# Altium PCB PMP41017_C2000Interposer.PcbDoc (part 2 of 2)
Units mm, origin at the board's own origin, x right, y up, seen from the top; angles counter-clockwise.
Board outline 70 x 48.62 mm, 4 copper layers (Top, Mid1, Mid2, Bottom), stack 0.778 mm thick; 159 components, 259 nets, 698 pads, 194 vias.
Unrouted connection lines stored in the file: 8.
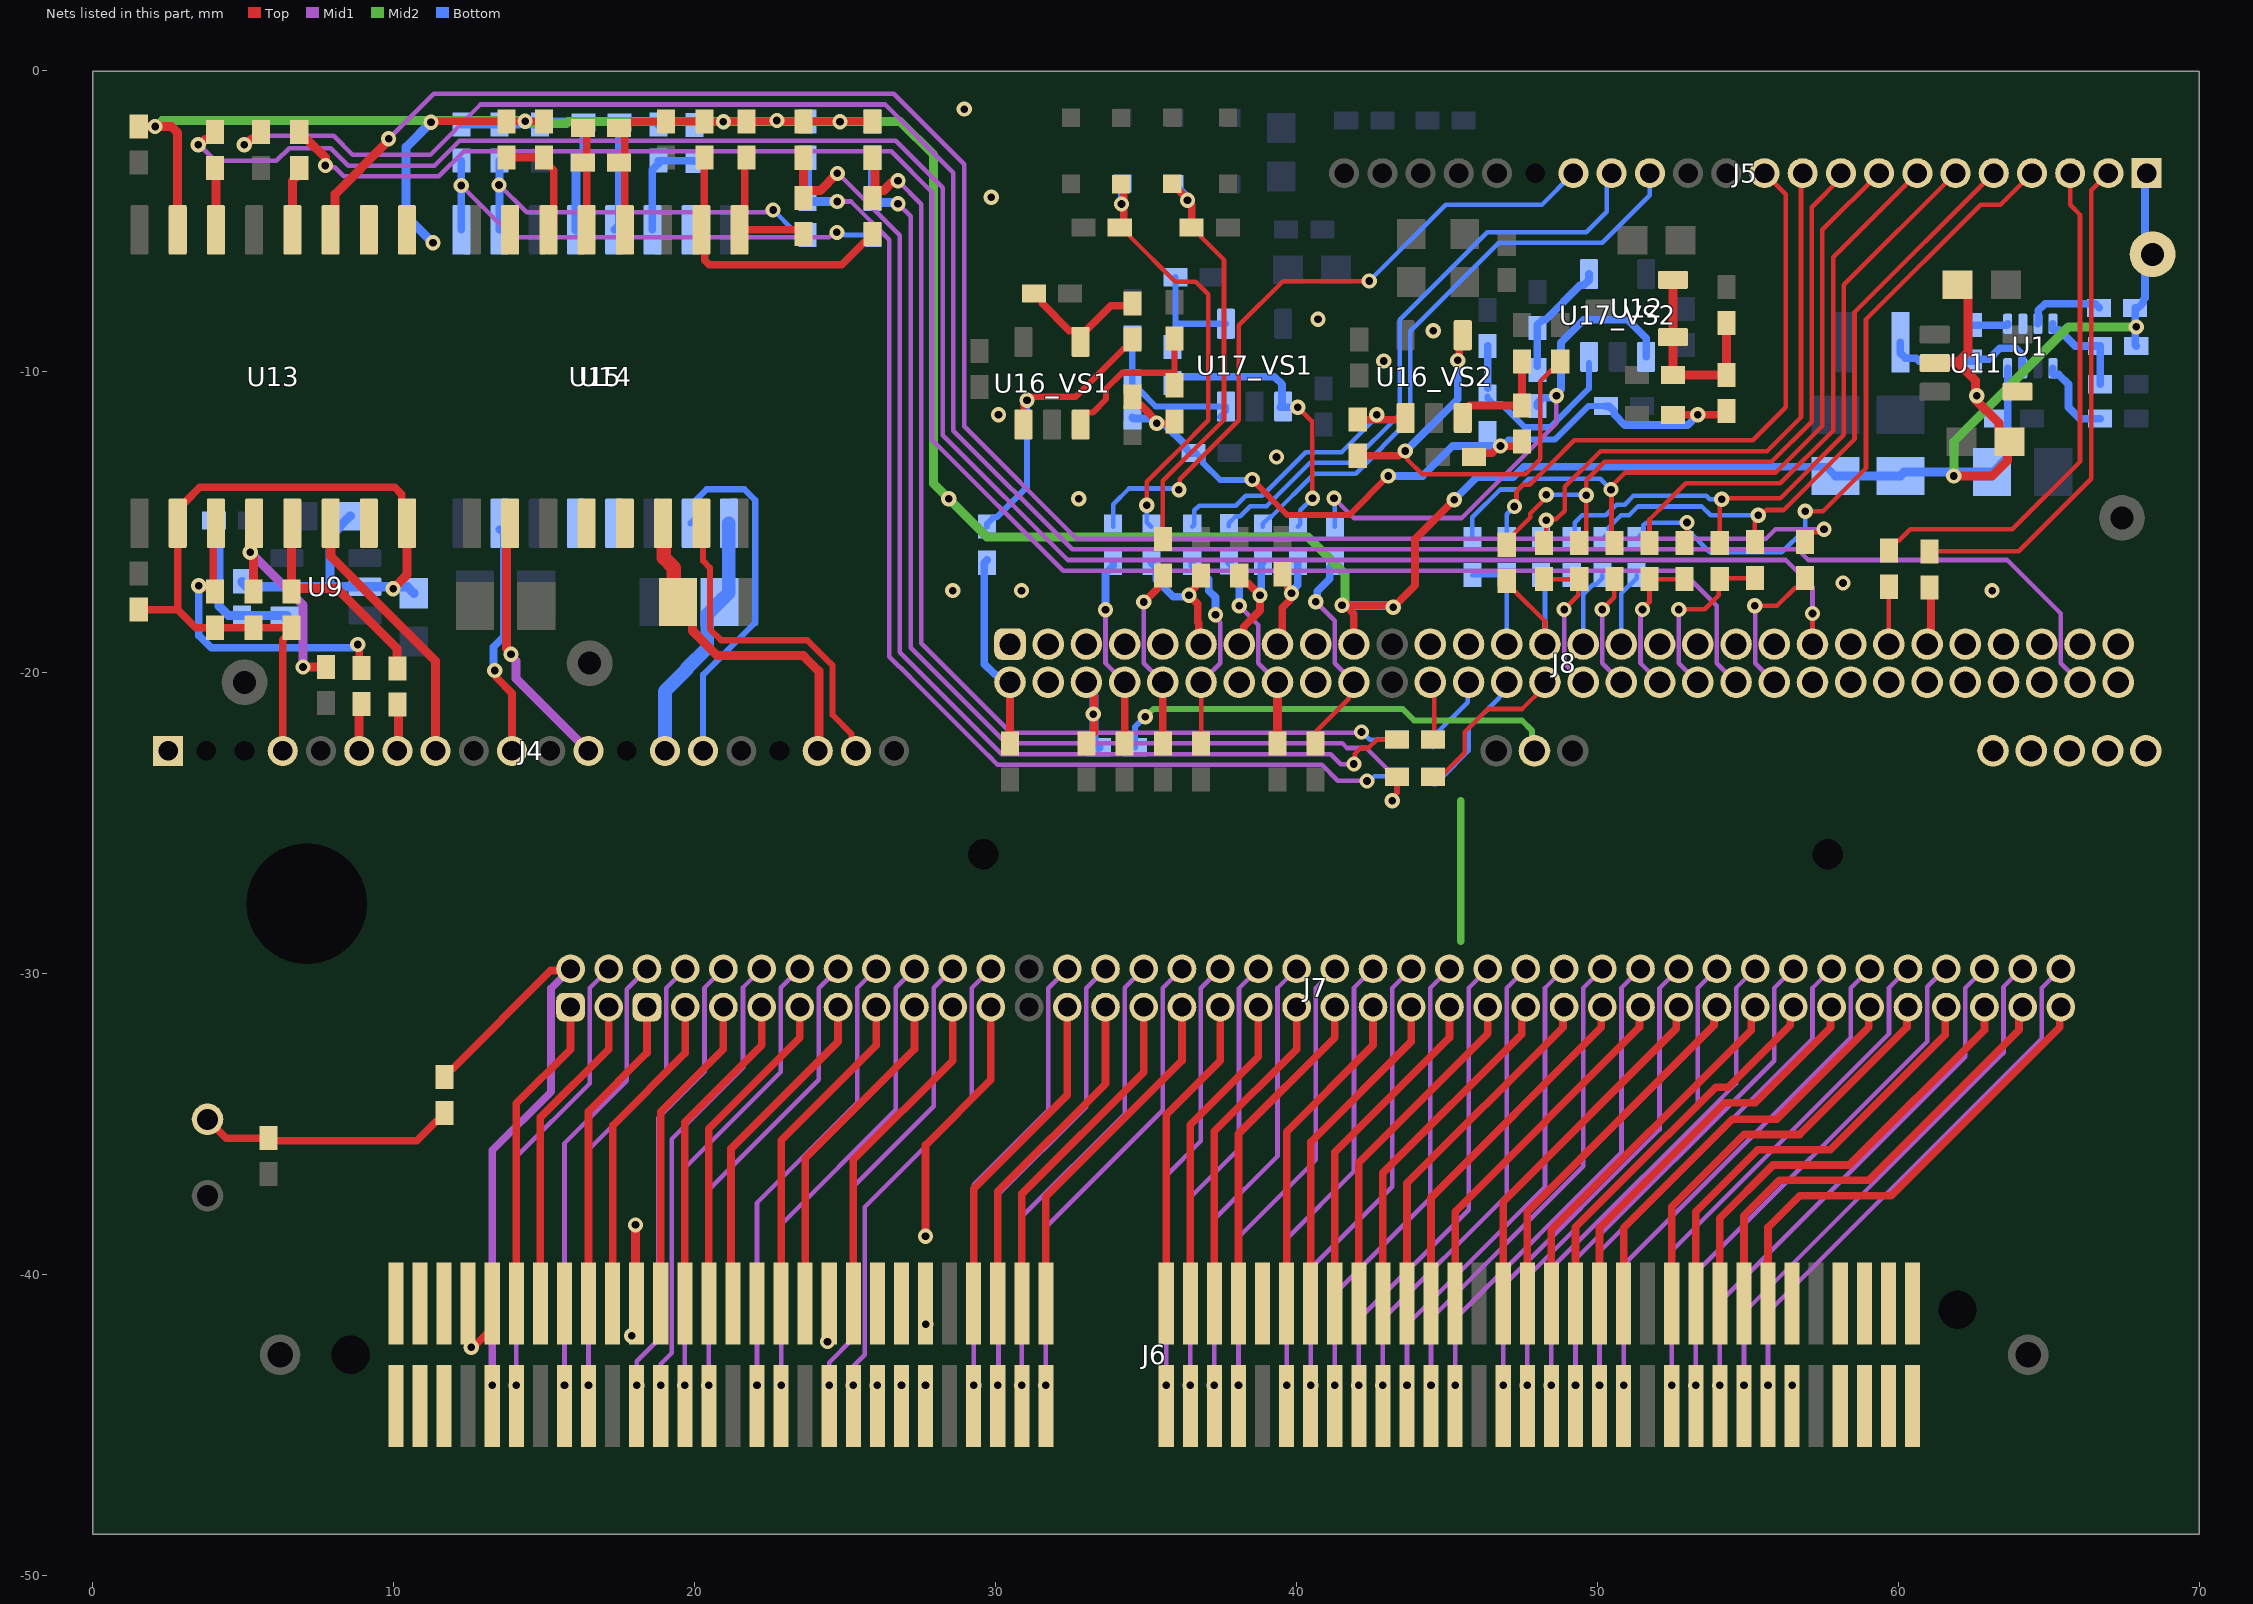
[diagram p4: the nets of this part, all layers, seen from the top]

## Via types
v1: diameter 0.508, hole 0.254, Top to Bottom, tented both sides, 194 vias

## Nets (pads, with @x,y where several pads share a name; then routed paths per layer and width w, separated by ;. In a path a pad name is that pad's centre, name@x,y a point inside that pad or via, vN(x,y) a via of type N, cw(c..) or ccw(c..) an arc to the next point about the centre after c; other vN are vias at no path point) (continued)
DGND-s: C1.1 C2.2 C5.2 C6.2 C105.2 C107.2 C111.2 C112.2 C113.2 C114.2 C115.2 C118.2 C119.2 C125.1 C126.1 C127.2 C128.2 J5.1 J6.10 J6.22 J6.38 J6.46 J7.23 J8.23 pad.5@63.15,-22.6 pad.5@64.42,-22.6 pad.5@65.69,-22.6 pad.5@66.96,-22.6 pad.5@68.23,-22.6 pad.9@68.453,-6.096 R3.1 R20.2 R68.2 R69.2 R70.2 R71.2 R79.1 R80.1 R81.1 R82.1 U1.4 U11.2 U13.15 U14.4 U15.4 | length 179.7
  Top w0.152: J6.22@18.034,-40.933 J6.22@18.073,-40.972 ; J6.46@27.673,-40.972 27.681,-40.98 v1(27.681,-41.656) J6.46@27.681,-41.739
  Top w0.254: v1(11.238,-1.709) 11.269,-1.677 C125.1@13.742,-1.677 R81.1@14.986,-1.677 ; v1(12.573,-42.418) 12.638,-42.418 13.273,-41.783 J6.10@13.273,-40.972 ; R79.1@17.491,-1.905 17.664,-1.732 17.867,-1.732 17.913,-1.686 19.041,-1.686 C127.2@19.05,-1.677 C112.2@20.32,-1.677 20.329,-1.686 v1(20.955,-1.686) ; R79.1@17.507,-1.905 17.68,-2.078 U14.4@17.68,-5.285 ; v1@20.946,-1.677 C111.2@21.717,-1.677 25.899,-1.677 R68.2@25.908,-1.686 ; v1(27.673,-38.735) 27.673,-35.7 29.845,-33.528 J7.23@29.845,-31.115 ; v1@41.496,-17.778 41.651,-17.778 41.91,-18.037 J8.23@41.91,-19.05 ; v1@41.496,-17.745 v1(41.512,-17.761) ; v1@41.651,-17.761 43.079,-17.761 43.145,-17.828 v1(43.214,-17.828) 43.942,-17.1 43.942,-15.558 v1(45.244,-14.256) v1@45.212,-14.224
  Top w0.3: C115.2@1.524,-1.848 2.61,-1.848 2.82,-2.058 U13.15@2.82,-5.285 ; v1(17.907,-42.037) 17.907,-41.981 18.006,-41.882 18.006,-41.039 J6.22@18.073,-40.972 ; J6.22@18.034,-40.933 v1(18.034,-38.354) ; v1(24.413,-42.231) 24.413,-42.175 24.473,-42.115 J6.38@24.473,-40.972 ; v1(61.849,-13.462) 63.119,-13.462 63.627,-12.954 63.627,-12.395 C107.2@63.703,-12.319 63.678,-12.319 63.353,-11.994 63.353,-11.708 62.567,-10.922 62.567,-10.287 61.993,-9.713 U11.2@61.214,-9.713 61.25,-9.677 61.985,-9.677 62.313,-9.349 C105.2@62.313,-7.437
  Mid2 w0.254: 45.466,-28.921 45.466,-24.257
  Mid2 w0.3: v1(2.067,-1.848) 2.123,-1.848 2.32,-1.651 11.124,-1.651 11.181,-1.709 v1(11.238,-1.709) 11.277,-1.669 11.424,-1.669 11.442,-1.651 v1@14.431,-1.651 ; v1(14.364,-1.677) 14.404,-1.717 14.551,-1.717 14.578,-1.744 15.736,-1.744 15.794,-1.686 v1(20.955,-1.686) 22.733,-1.686 v1(24.828,-1.686) 26.832,-1.686 27.94,-2.794 27.94,-13.716 29.718,-15.494 40.386,-15.494 41.616,-16.724 41.616,-17.601 41.512,-17.705 v1(41.512,-17.761) ; v1(61.849,-13.462) 61.849,-12.319 65.659,-8.509 v1(67.91,-8.509)
  Bottom w0.254: C113.2@12.245,-1.784 14.175,-1.784 14.233,-1.726 14.316,-1.726 v1(14.364,-1.677) ; v1@14.471,-1.784 C128.2@14.863,-1.784 14.97,-1.677 16.256,-1.677 R80.1@16.299,-1.72 C119.2@16.299,-3.028 ; v1(20.955,-1.686) R70.2@23.749,-1.686 R71.2@25.908,-1.686 ; v1(45.244,-14.256) 45.991,-13.509 47.199,-13.509 47.555,-13.154 57.604,-13.154 C6.2@57.912,-13.462 ; C2.2@63.119,-13.335 63.627,-12.827 63.627,-12.525 63.639,-12.513 U1.4@63.639,-9.884 ; R20.2@67.91,-9.144 67.875,-9.109 67.875,-8.509 R3.1@67.875,-7.874 67.975,-7.874 68.148,-7.701 68.148,-7.601 68.199,-7.55 68.199,-3.456 J5.1@68.255,-3.4
  Bottom w0.3: v1(2.067,-1.848) 2.123,-1.848 2.32,-1.651 11.033,-1.651 11.051,-1.669 11.198,-1.669 v1(11.238,-1.709) 10.414,-2.532 10.414,-4.826 v1(11.303,-5.715) ; U15.4@16.055,-5.285 16.055,-3.198 16.225,-3.028 C119.2@16.299,-3.028 ; C126.1@18.796,-1.784 18.894,-1.686 v1(20.955,-1.686) ; v1(41.512,-17.761) 41.526,-17.775 43.105,-17.775 43.158,-17.828 v1(43.214,-17.828) ; C6.2@57.912,-13.462 C5.2@60.071,-13.462 60.198,-13.335 C2.2@63.119,-13.335
  other v1: 28.575,-17.272 30.861,-17.272 63.119,-17.272 58.166,-17.018 28.448,-14.224 32.766,-14.224 39.339,-12.831 30.099,-11.43 62.611,-10.795 42.9,-9.643 44.543,-8.639 40.716,-8.255 29.861,-4.203 22.733,-1.651 28.956,-1.27
GNDc-p: C77.2 C88.2 C110.2 C120.1 C121.1 C122.1 J4.4 R5.1 U9.2 U13.2 U13.8 | length 32.8
  Top w0.254: C110.2@1.47,-17.907 2.82,-17.907 ; J4.4@6.31,-22.6 6.31,-18.901 6.604,-18.607 C120.1@6.604,-18.507 C121.1@5.334,-18.507 C122.1@4.064,-18.507 3.42,-18.507 2.82,-17.907 ; U13.8@10.44,-15.035 10.27,-14.864 10.27,-14.08 10.033,-13.843 3.556,-13.843 3.062,-14.337 2.993,-14.337 2.82,-14.51 U13.2@2.82,-15.035 2.82,-17.907
  Top w0.3: v1(9.978,-17.207) 9.978,-17.204 10.44,-16.742 U13.8@10.44,-15.035
  Bottom w0.3: R5.1@4.953,-16.963 4.953,-16.995 5.103,-17.145 7.874,-17.145 ; C88.2@8.566,-14.799 8.541,-14.799 8.216,-15.124 8.216,-15.149 7.874,-15.491 7.874,-17.145 ; C77.2@10.668,-17.361 10.452,-17.145 9.978,-17.145 U9.2@9.047,-17.145 7.874,-17.145
HV_BUS: J4.1
I-reso_VS1: D3_VS1.1 D5_VS1.1 R11.2 R83_VS1.2 | length 14.7
  Top w0.152: R83_VS1.2@34.128,-5.207 34.228,-5.207 34.452,-5.431 34.452,-5.486 35.976,-7.011 36.655,-7.011 37.068,-7.424 37.068,-11.617 36.086,-12.599 35.56,-13.125 35.027,-13.659 v1(35.027,-14.437)
  Top w0.203: R83_VS1.2@34.128,-5.207 R83_VS1.2@34.262,-5.073
  Top w0.254: R83_VS1.2@34.262,-5.073 34.262,-4.426 D5_VS1.1@34.262,-3.767
  Bottom w0.152: v1(35.027,-14.437) 35.027,-14.996 R11.2@35.179,-15.148
  Bottom w0.203: v1(34.185,-4.426) 34.213,-4.426 v1@34.199,-4.412 ; D3_VS1.1@34.199,-3.762 D3_VS1.1@34.213,-3.748
  Bottom w0.254: v1@34.199,-4.412 D3_VS1.1@34.199,-3.762
I-reso_VS2: D3_VS2.1 D5_VS2.1 R12.2 R83_VS2.2 | length 14
  Top w0.152: R12.2@35.56,-15.564 35.56,-13.628 37.592,-11.596 37.592,-6.28 36.843,-5.531 36.843,-5.431 36.619,-5.207 R83_VS2.2@36.519,-5.207
  Top w0.203: R83_VS2.2@36.519,-5.207 R83_VS2.2@36.519,-5.073
  Top w0.254: D5_VS2.1@35.872,-3.751 v1@36.323,-4.202 ; v1(36.38,-4.302) 36.519,-4.441 R83_VS2.2@36.519,-5.073
  Bottom w0.254: D3_VS2.1@35.941,-3.767 36.331,-4.157 36.331,-4.254 v1(36.38,-4.302)
ISEC1: J5.15 R13.2 | length 20.1
  Bottom w0.152: R13.2@37.752,-15.134 37.752,-15.034 37.976,-14.811 38.06,-14.811 38.065,-14.806 38.134,-14.806 38.468,-14.472 39.006,-14.472 40.45,-13.028 41.822,-13.028 43.43,-11.42 43.43,-8.266 46.337,-5.359 49.632,-5.359 50.315,-4.676 50.315,-3.56 J5.15@50.475,-3.4
ISEC2: J5.14 R14.2 | length 19.9
  Bottom w0.152: R14.2@38.884,-15.151 38.884,-15.051 39.107,-14.827 39.154,-14.827 40.597,-13.383 41.965,-13.383 43.783,-11.566 43.783,-8.65 46.717,-5.715 50.165,-5.715 51.745,-4.135 J5.14@51.745,-3.4
LLC-DRV-1H: J4.19 U14.15 | length 10.8
  Top w0.203: U14.15@20.281,-15.621 20.281,-16.284 20.507,-16.51 20.507,-18.551 20.88,-18.923 23.749,-18.923 24.511,-19.685 24.511,-19.69 24.582,-19.76 24.582,-21.407 25.208,-22.033 25.208,-22.448 J4.19@25.36,-22.6
LLC-DRV-1L: J4.12 U14.10 | length 8.9
  Top w0.3: U14.10@13.87,-15.035 13.744,-15.161 13.744,-19.181 13.897,-19.334 v1(13.897,-19.39) ; J4.12@16.47,-22.6 J4.12@16.47,-22.411
  Mid1 w0.3: v1(13.897,-19.39) 13.897,-19.446 14.065,-19.614 14.065,-20.195 J4.12@16.47,-22.6
LLC-DRV-2H: J4.15 U15.10 | length 12.2
  Bottom w0.203: U15.10@19.865,-15.035 20.064,-14.837 20.064,-14.241 20.4,-13.905 21.652,-13.905 22.014,-14.267 22.014,-18.333 20.28,-20.067 J4.15@20.28,-22.6
LLC-DRV-2L: J4.10 U15.15 | length 7.8
  Top w0.254: v1(13.358,-19.929) 13.407,-19.977 13.407,-20.157 13.93,-20.68 J4.10@13.93,-22.6
  Bottom w0.254: v1(13.358,-19.929) 13.313,-19.883 13.313,-19.148 13.665,-18.796 13.665,-15.39 U15.15@13.515,-15.24
LLC-SW1: C116.2 J4.18 U14.14 | length 11.4
  Top w0.3: C116.2@19.444,-17.653 19.929,-18.138 19.929,-18.615 20.744,-19.431 23.614,-19.431 24.13,-19.947 24.13,-22.56 J4.18@24.09,-22.6
  Top w0.483: U14.14@18.95,-15.035 18.966,-15.051 18.966,-16.172 19.304,-16.51 19.304,-17.513 C116.2@19.444,-17.653
LLC-SW2: C117.2 J4.14 U15.9 | length 8.4
  Bottom w0.457: J4.14@19.01,-22.6 19.01,-20.614 19.747,-19.877 19.747,-19.846 20.422,-19.171 20.422,-18.059 C117.2@20.828,-17.653 21.135,-17.346 U15.9@21.135,-15.035
MCU_A1: J6.11 J7.4 | length 15.1
  Mid1 w0.152: v1(14.073,-43.688) 14.073,-36.092 16.51,-33.655 16.51,-30.48 J7.4@17.145,-29.845
MCU_A3: J6.39 J7.24 | length 15.7
  Mid1 w0.152: v1(25.273,-43.688) 25.273,-43.053 25.654,-42.672 25.654,-37.757 29.21,-34.201 29.21,-30.48 J7.24@29.845,-29.845
MCU_A3_1: C89.2 J8.24 R18.1 | length 7.4
  Top w0.152: C89.2@40.457,-22.352 40.681,-22.128 40.681,-21.93 41.738,-20.873 41.738,-20.492 J8.24@41.91,-20.32
  Mid1 w0.152: v1(40.64,-17.643) 41.276,-18.279 41.276,-19.686 J8.24@41.91,-20.32
  Bottom w0.254: v1(40.64,-17.643) 40.686,-17.597 40.686,-17.3 41.102,-16.884 41.102,-16.521 R18.1@41.275,-16.348
MCU_A4: J6.17 J7.8 | length 15.2
  Mid1 w0.152: v1(16.473,-43.688) 16.473,-35.851 19.05,-33.274 19.05,-30.48 J7.8@19.685,-29.845
MCU_A4_1: J8.8
MCU_A5: J6.21 J7.10 | length 15
  Mid1 w0.152: v1(18.073,-43.688) 18.073,-42.887 18.796,-42.164 18.796,-34.798 20.327,-33.267 20.327,-30.473 J7.10@20.955,-29.845
MCU_A5_1: C74.2 J8.10 R1.1 | length 4.6
  Top w0.254: C74.2@33.02,-22.352 33.02,-22.252 33.274,-21.998 33.274,-20.789 33.02,-20.535 J8.10@33.02,-20.32
  Bottom w0.3: J8.10@33.02,-20.32 33.02,-20.523 33.274,-20.777 33.274,-22.329 33.424,-22.479 R1.1@33.436,-22.479
  other v1: 33.247,-21.376
MCU_A6: J6.23 J7.12 | length 15.2
  Mid1 w0.152: v1(18.873,-43.688) 18.873,-42.976 19.24,-42.609 19.24,-35.497 21.606,-33.131 21.606,-30.464 J7.12@22.225,-29.845
MCU_A6_1: C75.2 J8.12 R2.1 | length 6.4
  Top w0.254: C75.2@34.29,-22.352 J8.12@34.29,-20.32
  Mid1 w0.152: v1(33.655,-17.907) 33.655,-19.685 J8.12@34.29,-20.32
  Bottom w0.254: v1(33.655,-17.907) 33.655,-16.702 33.909,-16.448 R2.1@33.909,-16.348
MCU_A7: J6.33 J7.20 | length 15.7
  Mid1 w0.152: v1(22.873,-43.688) 22.873,-38.341 26.682,-34.532 26.682,-30.468 J7.20@27.305,-29.845
MCU_A7_1: C82.2 J8.20 R13.1 | length 6.7
  Top w0.3: C82.2@39.37,-22.352 J8.20@39.37,-20.32
  Mid1 w0.152: v1(38.1,-17.78) 38.736,-18.416 38.736,-19.686 J8.20@39.37,-20.32
  Bottom w0.254: R13.1@37.752,-16.334 37.925,-16.507 37.925,-16.708 38.1,-16.883 v1(38.1,-17.78)
MCU_A8: J6.30 J7.15 | length 11.4
  Top w0.254: J6.30@21.273,-40.972 21.209,-40.908 21.209,-35.814 24.765,-32.258 J7.15@24.765,-31.115
MCU_A8_1: C76.2 J8.15 R11.1 | length 4.8
  Top w0.254: J8.15@36.83,-19.05 36.758,-18.978 36.758,-18.349 36.725,-18.315 36.725,-17.719 v1(36.43,-17.424) 36.43,-17.375 36.657,-17.148 36.657,-16.937 C76.2@36.83,-16.764
  Bottom w0.254: R11.1@35.179,-16.348 35.344,-16.513 35.344,-16.914 35.902,-17.472 36.381,-17.472 v1(36.43,-17.424) ; J8.15@36.83,-19.05 J8.15@36.83,-18.835
MCU_A9: J6.34 J7.17 | length 11.2
  Top w0.254: J6.34@22.873,-40.972 22.873,-35.547 26.035,-32.385 J7.17@26.035,-31.115
MCU_A9_1: C84.2 J8.17 R14.1 | length 4.3
  Top w0.254: J8.17@38.1,-19.05 38.252,-18.898 38.252,-18.469 38.788,-17.934 v1(38.788,-17.424) 38.401,-17.037 38.273,-17.037 38.1,-16.864 C84.2@38.1,-16.764
  Bottom w0.254: J8.17@38.1,-19.05 J8.17@38.1,-18.835 ; v1(38.788,-17.424) 38.836,-17.376 38.836,-16.399 R14.1@38.884,-16.351
MCU_A10: J6.25 J7.14 | length 15.4
  Mid1 w0.152: v1(19.673,-43.688) 19.673,-36.461 22.862,-33.272 22.862,-30.478 J7.14@23.495,-29.845
MCU_A10_1: C78.2 J8.14 R12.1 | length 6.1
  Top w0.254: v1(34.926,-17.653) 35.387,-17.192 35.387,-16.937 R12.1@35.56,-16.764 ; C78.2@35.56,-22.352 J8.14@35.56,-20.32
  Mid1 w0.152: v1(34.926,-17.653) 34.926,-19.686 J8.14@35.56,-20.32
MCU_A12: J6.37 J7.22 | length 15.5
  Mid1 w0.152: v1(24.473,-43.688) 24.473,-42.926 25.273,-42.126 25.273,-37.084 27.942,-34.415 27.942,-30.478 J7.22@28.575,-29.845
MCU_A12_1: J8.22
MCU_B0: J6.31 J7.18 | length 15.5
  Mid1 w0.152: v1(22.073,-43.688) 22.073,-37.617 25.4,-34.29 25.4,-30.48 J7.18@26.035,-29.845
MCU_B0_1: J8.18
MCU_B2: J6.14 J7.3 | length 10.8
  Top w0.254: J6.14@14.873,-40.972 14.873,-34.784 17.145,-32.512 J7.3@17.145,-31.115
MCU_B3: J6.12 J7.1 | length 10.6
  Top w0.254: J6.12@14.073,-40.972 14.073,-34.314 15.875,-32.512 J7.1@15.875,-31.115
MCU_B4: J6.20 J7.7 | length 10.9
  Top w0.254: J6.20@17.273,-40.972 17.272,-40.971 17.272,-35.052 19.685,-32.639 J7.7@19.685,-31.115
MCU_B4_1: J8.7
MCU_B5: J6.26 J7.11 | length 10.9
  Top w0.254: J6.26@19.673,-40.972 19.673,-34.937 22.225,-32.385 J7.11@22.225,-31.115
MCU_B5_1: J8.11
MCU_B6: J6.15 J7.6 | length 15
  Mid1 w0.152: v1(15.673,-43.688) 15.673,-35.635 17.742,-33.566 17.742,-30.518 J7.6@18.415,-29.845
MCU_B6_1: C85.2 J8.6 R15.1 | length 6.6
  Top w0.254: C85.2@30.48,-22.352 J8.6@30.48,-20.32
  Bottom w0.254: R15.1@29.718,-16.256 29.625,-16.349 29.625,-19.712 29.97,-20.057 30.001,-20.057 30.265,-20.32 J8.6@30.48,-20.32
MCU_B10: J6.27 J7.16 | length 15.6
  Mid1 w0.152: v1(20.473,-43.688) 20.473,-37.185 24.123,-33.535 24.123,-30.487 J7.16@24.765,-29.845
MCU_B10_1: C87.2 J8.16 R17.1 | length 6.7
  Top w0.152: C87.2@36.83,-22.352 J8.16@36.83,-20.32
  Mid1 w0.152: J8.16@36.83,-20.32 37.464,-19.686 37.464,-18.325 37.309,-18.17 v1(37.309,-18.073)
  Bottom w0.254: R17.1@36.537,-16.348 36.537,-16.448 36.71,-16.621 36.81,-16.621 37.084,-16.895 37.084,-17.274 37.309,-17.499 v1(37.309,-18.073)
MCU_B11: J6.24 J7.9 | length 10.7
  Top w0.254: J6.24@18.873,-40.972 18.873,-34.594 20.955,-32.512 J7.9@20.955,-31.115
MCU_B11_1: J8.9
MCU_B12: J6.18 J7.5 | length 10.7
  Top w0.254: J6.18@16.473,-40.972 16.473,-34.581 18.415,-32.639 J7.5@18.415,-31.115
MCU_B12_1: J8.5
MCU_B14: J6.36 J7.19 | length 11.4
  Top w0.254: J6.36@23.673,-40.972 23.673,-36.144 27.305,-32.512 J7.19@27.305,-31.115
MCU_B14_1: C86.2 J8.19 R16.1 | length 3.6
  Top w0.254: J8.19@39.37,-19.05 39.522,-18.898 39.522,-17.84 39.789,-17.573 39.789,-17.338 39.838,-17.29 39.716,-17.168 39.716,-17.002 39.616,-16.902 C86.2@39.543,-16.902
  Bottom w0.254: v1(39.838,-17.359) 39.838,-17.302 40.047,-17.092 R16.1@40.047,-16.348
MCU_C1: J6.28 J7.13 | length 11.1
  Top w0.254: J6.28@20.473,-40.972 20.473,-35.153 23.495,-32.131 J7.13@23.495,-31.115
MCU_C1_1: J8.13
MCU_C14: J6.40 J7.21 | length 11.2
  Top w0.254: J6.40@25.273,-40.972 25.273,-36.195 28.575,-32.893 J7.21@28.575,-31.115
MCU_C14_1: J8.21
MCU_DACA: J6.9 J7.2 R60.2 | length 20.7
  Top w0.254: R60.2@11.684,-33.436 11.684,-33.336 11.857,-33.163 11.957,-33.163 15.223,-29.897 15.823,-29.897 J7.2@15.875,-29.845
  Mid1 w0.254: v1(13.273,-43.688) 13.273,-35.876 15.227,-33.922 15.227,-30.493 J7.2@15.875,-29.845
MCU_EMU0_3: J6.2
MCU_EMU1_3: J6.1
MCU_GPIO0: J6.49 J7.28 | length 15.1
  Mid1 w0.152: v1(29.273,-43.688) 29.273,-37.021 31.747,-34.547 31.747,-30.483 J7.28@32.385,-29.845
MCU_GPIO0_1: J8.28 R30.2 | length 2
  Top w0.152: J8.28@44.45,-20.32 44.577,-20.447 44.577,-22.19 R30.2@44.542,-22.225
MCU_GPIO1: J6.51 J7.30 | length 15.3
  Mid1 w0.152: v1(30.073,-43.688) 30.099,-43.662 30.099,-37.338 33.009,-34.428 33.009,-30.491 J7.30@33.655,-29.845
MCU_GPIO1_1: J8.30 R32.2 | length 2.6
  Bottom w0.152: R32.2@44.542,-22.479 44.635,-22.386 44.635,-22.04 45.691,-20.984 45.691,-20.349 J8.30@45.72,-20.32
MCU_GPIO2: J6.53 J7.32 | length 15.5
  Mid1 w0.152: v1(30.873,-43.688) 30.873,-38.088 34.292,-34.669 34.292,-30.478 J7.32@34.925,-29.845
MCU_GPIO2_1: J8.32 R33.2 | length 4.5
  Bottom w0.152: R33.2@44.542,-23.7 44.642,-23.7 44.866,-23.477 44.866,-23.454 45.72,-22.6 45.72,-21.844 46.737,-20.827 46.737,-20.816 46.99,-20.563 J8.32@46.99,-20.32
MCU_GPIO3: J6.55 J7.34 | length 15.7
  Mid1 w0.152: v1(31.673,-43.688) 31.673,-38.431 35.56,-34.544 35.56,-30.48 J7.34@36.195,-29.845
MCU_GPIO3_1: J8.34 R35.2 | length 5.6
  Top w0.152: R35.2@44.542,-23.465 44.612,-23.395 44.866,-23.395 45.593,-22.668 45.593,-21.971 46.355,-21.209 47.498,-21.209 48.26,-20.447 J8.34@48.26,-20.32
  Bottom w0.152: J8.34@48.128,-20.32 J8.34@48.26,-20.32
MCU_GPIO4: J6.50 J7.27 | length 11.1
  Top w0.254: J6.50@29.273,-40.972 29.273,-37.148 32.385,-34.036 J7.27@32.385,-31.115
MCU_GPIO4_1: J8.27
MCU_GPIO5: J6.52 J7.29 | length 11.3
  Top w0.254: J6.52@30.073,-40.972 30.073,-37.237 33.655,-33.655 J7.29@33.655,-31.115
MCU_GPIO5_1: J8.29
MCU_GPIO6: J6.54 J7.31 | length 11.5
  Top w0.254: J6.54@30.873,-40.972 30.873,-37.326 34.925,-33.274 J7.31@34.925,-31.115
MCU_GPIO6_1: J8.31 R7.2 R99.2 | length 3.4
  Bottom w0.152: R7.2@45.847,-16.756 R99.2@46.99,-16.756 J8.31@46.99,-19.05
MCU_GPIO7: J6.56 J7.33 | length 11.7
  Top w0.254: J6.56@31.673,-40.972 31.673,-37.415 36.195,-32.893 J7.33@36.195,-31.115
MCU_GPIO7_1: J8.33 R23.2 R100.2 | length 5.2
  Top w0.152: R23.2@46.99,-16.948 46.99,-17.048 47.214,-17.272 47.244,-17.272 48.26,-18.288 J8.33@48.26,-19.05
  Bottom w0.152: R100.2@48.133,-16.756 48.26,-16.883 J8.33@48.26,-19.05
  Bottom w0.254: J8.33@48.133,-18.923 J8.33@48.26,-19.05
MCU_GPIO8: J6.57 J7.36 | length 14.6
  Mid1 w0.152: v1(35.673,-43.688) 35.673,-36.717 36.825,-35.565 36.825,-30.485 J7.36@37.465,-29.845
MCU_GPIO8_1: J8.36 R8.2 R37.2 | length 5.1
  Top w0.152: R8.2@48.231,-16.891 48.814,-16.891 R37.2@49.398,-16.891 49.364,-16.925 49.364,-17.43 v1(48.895,-17.899)
  Mid1 w0.152: v1(48.895,-17.899) 48.895,-19.685 J8.36@49.53,-20.32
MCU_GPIO9: J6.59 J7.38 | length 14.8
  Mid1 w0.152: v1(36.473,-43.688) 36.473,-37.441 38.092,-35.822 38.092,-30.488 J7.38@38.735,-29.845
MCU_GPIO9_1: J8.38 R38.2 | length 3.9
  Top w0.152: v1(50.165,-17.899) 50.565,-17.498 R38.2@50.565,-16.891
  Mid1 w0.152: v1(50.165,-17.899) 50.165,-19.685 J8.38@50.8,-20.32
MCU_GPIO10: J6.61 J7.40 | length 15
  Mid1 w0.152: v1(37.273,-43.688) 37.273,-38.165 39.37,-36.068 39.37,-30.48 J7.40@40.005,-29.845
MCU_GPIO10_1: J8.40 R9.2 R40.2 | length 5.3
  Top w0.152: R9.2@52.9,-16.891 R40.2@51.733,-16.891 51.733,-17.632 ; 51.733,-17.632 51.733,-17.665 v1(51.499,-17.899) 51.499,-17.866 51.733,-17.632
  Mid1 w0.152: v1(51.499,-17.899) 51.436,-17.962 51.436,-19.686 J8.40@52.07,-20.32
MCU_GPIO11: J6.63 J7.42 | length 15.2
  Mid1 w0.152: v1(38.073,-43.688) 38.073,-38.762 40.64,-36.195 40.64,-30.48 J7.42@41.275,-29.845
MCU_GPIO11_1: J8.42 R24.2 R41.2 | length 5.9
  Top w0.152: v1(52.706,-17.899) 53.567,-17.899 54.035,-17.43 54.035,-16.924 R41.2@54.068,-16.891 54.103,-16.856 R24.2@55.235,-16.856
  Mid1 w0.152: v1(52.706,-17.899) 52.706,-19.686 J8.42@53.34,-20.32
MCU_GPIO12: J6.58 J7.35 | length 10.6
  Top w0.254: J6.58@35.673,-40.972 35.673,-34.685 37.465,-32.893 J7.35@37.465,-31.115
MCU_GPIO12_1: J8.35 R10.2 R101.2 | length 3.3
  Bottom w0.152: R10.2@49.149,-16.856 49.53,-17.237 49.53,-17.391 ; J8.35@49.53,-19.05 49.53,-17.391 ; R101.2@50.165,-16.756 50.165,-16.856 49.941,-17.08 49.841,-17.08 49.53,-17.391
MCU_GPIO13: J6.60 J7.37 | length 10.8
  Top w0.254: J6.60@36.473,-40.972 36.473,-35.028 38.735,-32.766 J7.37@38.735,-31.115
MCU_GPIO13_1: J8.37 R102.2 | length 2.5
  Bottom w0.152: J8.37@50.8,-19.05 50.8,-17.364 51.308,-16.856 R102.2@51.308,-16.756
MCU_GPIO14: J6.62 J7.39 | length 11
  Top w0.254: J6.62@37.273,-40.972 37.273,-35.244 40.005,-32.512 J7.39@40.005,-31.115
MCU_GPIO14_1: J8.39
MCU_GPIO15: J6.64 J7.41 | length 11.2
  Top w0.254: J6.64@38.073,-40.972 38.073,-35.333 41.275,-32.131 J7.41@41.275,-31.115
MCU_GPIO15_1: J8.41
MCU_GPIO16: J6.67 J7.44 | length 15
  Mid1 w0.152: v1(39.673,-43.688) 39.673,-38.813 41.912,-36.574 41.912,-30.478 J7.44@42.545,-29.845
MCU_GPIO16_1: J8.44 R46.2 | length 62.2
  Top w0.3: R46.2@6.858,-2.032 6.858,-2.132 7.008,-2.282 7.123,-2.282 7.733,-2.891 7.733,-3.139 v1(7.728,-3.143)
  Mid1 w0.152: v1(7.728,-3.143) 7.791,-3.206 8.043,-3.206 8.341,-3.505 11.501,-3.505 12.333,-2.673 26.534,-2.673 27.889,-4.028 27.889,-12.253 32.248,-16.612 52.807,-16.612 53.975,-17.78 53.975,-19.685 J8.44@54.61,-20.32
MCU_GPIO17: J6.69 J7.46 | length 15.2
  Mid1 w0.152: v1(40.473,-43.688) 40.473,-39.791 43.18,-37.084 43.18,-30.48 J7.46@43.815,-29.845
MCU_GPIO17_1: J8.46 R48.1 | length 4.9
  Top w0.152: v1(55.235,-17.78) 55.972,-17.78 56.572,-17.18 56.672,-17.18 56.896,-16.956 R48.1@56.896,-16.856
  Mid1 w0.152: v1(55.235,-17.78) 55.246,-17.791 55.246,-19.686 J8.46@55.88,-20.32
MCU_GPIO18: J6.71 J7.48 | length 15.4
  Mid1 w0.152: v1(41.273,-43.688) 41.273,-40.642 44.45,-37.465 44.45,-30.48 J7.48@45.085,-29.845
MCU_GPIO18_1: J8.48
MCU_GPIO19: J6.73 J7.50 | length 15.6
  Mid1 w0.152: v1(42.073,-43.688) 42.073,-41.493 45.72,-37.846 45.72,-30.48 J7.50@46.355,-29.845
MCU_GPIO19_1: J8.50
MCU_GPIO20: J6.68 J7.43 | length 11
  Top w0.254: J6.68@39.673,-40.972 39.673,-35.257 42.545,-32.385 J7.43@42.545,-31.115
MCU_GPIO20_1: J8.43
MCU_GPIO21: J6.70 J7.45 | length 11.2
  Top w0.254: J6.70@40.473,-40.972 40.473,-35.6 43.815,-32.258 J7.45@43.815,-31.115
MCU_GPIO21_1: J8.45
MCU_GPIO22: J6.72 J7.47 | length 11.4
  Top w0.254: J6.72@41.273,-40.972 41.273,-35.943 45.085,-32.131 J7.47@45.085,-31.115
MCU_GPIO22_1: J8.47 R43.2 | length 68.3
  Top w0.152: J8.47@57.15,-19.05 v1(57.15,-18.034)
  Top w0.3: v1(3.505,-2.455) 3.561,-2.455 3.735,-2.282 3.914,-2.282 4.064,-2.132 R43.2@4.064,-2.032
  Mid1 w0.152: v1(3.505,-2.455) 3.535,-2.455 4.069,-2.989 6.097,-2.989 6.52,-2.565 7.905,-2.565 8.489,-3.15 11.353,-3.15 12.186,-2.317 26.681,-2.317 28.245,-3.881 28.245,-12.106 32.395,-16.256 56.261,-16.256 57.15,-17.145 v1(57.15,-18.034)
MCU_GPIO23: J6.74 J7.49 | length 11.6
  Top w0.254: J6.74@42.073,-40.972 42.073,-36.286 46.355,-32.004 J7.49@46.355,-31.115
MCU_GPIO23_1: J8.49
MCU_GPIO24: J6.75 J7.52 | length 15.8
  Mid1 w0.152: v1(42.873,-43.688) 42.873,-41.493 46.99,-37.376 46.99,-30.48 J7.52@47.625,-29.845
MCU_GPIO24_1: J8.52
MCU_GPIO25: J6.77 J7.54 | length 16
  Mid1 w0.152: v1(43.673,-43.688) 43.673,-41.671 48.26,-37.084 48.26,-30.48 J7.54@48.895,-29.845
MCU_GPIO25_1: J8.54
MCU_GPIO26: J6.79 J7.56 | length 16.2
  Mid1 w0.152: v1(44.473,-43.688) 44.473,-41.468 49.53,-36.41 49.53,-30.48 J7.56@50.165,-29.845
MCU_GPIO26_1: J8.56
MCU_GPIO27: J6.81 J7.58 | length 16.4
  Mid1 w0.152: v1(45.273,-43.688) 45.273,-41.468 50.803,-35.938 50.803,-30.477 J7.58@51.435,-29.845
MCU_GPIO27_1: J8.58
MCU_GPIO28: J6.76 J7.51 | length 11.8
  Top w0.254: J6.76@42.873,-40.972 42.873,-36.629 47.491,-32.011 47.491,-31.249 J7.51@47.625,-31.115
MCU_GPIO28_1: J8.51 R50.2 | length 1.9
  Top w0.152: J8.51@59.69,-19.05 R50.2@59.69,-17.145
MCU_GPIO29: J6.78 J7.53 | length 12
  Top w0.254: J6.78@43.673,-40.972 43.673,-36.972 48.86,-31.785 48.86,-31.15 J7.53@48.895,-31.115
MCU_GPIO29_1: J8.53 R52.1 | length 1.5
  Top w0.254: J8.53@60.96,-19.05 61.087,-18.923 R52.1@61.087,-17.566
MCU_GPIO30: J6.80 J7.55 | length 12.2
  Top w0.254: J6.80@44.473,-40.972 44.473,-37.442 50.13,-31.785 50.13,-31.15 J7.55@50.165,-31.115
MCU_GPIO30_1: J8.55
MCU_GPIO31: J6.82 J7.57 | length 12.4
  Top w0.254: J6.82@45.273,-40.972 45.273,-37.912 51.4,-31.785 51.4,-31.15 J7.57@51.435,-31.115
MCU_GPIO31_1: J8.57
MCU_GPIO32: J6.85 J7.60 | length 16.3
  Mid1 w0.152: v1(46.873,-43.688) 46.873,-40.376 52.066,-35.183 52.066,-30.484 J7.60@52.705,-29.845
MCU_GPIO32_1: J8.60
MCU_GPIO33: J6.87 J7.62 | length 16.5
  Mid1 w0.152: v1(47.673,-43.688) 47.673,-40.084 53.34,-34.417 53.34,-30.48 J7.62@53.975,-29.845
MCU_GPIO33_1: J8.62 R45.2 | length 76.8
  Top w0.3: v1(5.029,-2.455) 5.085,-2.455 5.259,-2.282 5.438,-2.282 5.588,-2.132 R45.2@5.588,-2.032
  Mid1 w0.152: v1(5.029,-2.455) 5.325,-2.159 8.001,-2.159 8.636,-2.794 11.206,-2.794 12.882,-1.118 26.334,-1.118 28.6,-3.384 28.6,-11.958 32.543,-15.9 56.66,-15.9 57.015,-16.256 63.627,-16.256 65.404,-18.033 65.404,-19.684 J8.62@66.04,-20.32
MCU_GPIO34: J6.86 J7.59 | length 12.3
  Top w0.254: J6.86@46.873,-40.972 46.873,-37.582 52.628,-31.827 52.628,-31.192 J7.59@52.705,-31.115
MCU_GPIO34_1: J8.59
MCU_GPIO35: J6.90 J7.63 | length 12.7
  Top w0.254: J6.90@48.473,-40.972 48.473,-38.519 55.111,-31.88 55.111,-31.249 J7.63@55.245,-31.115
MCU_GPIO35_1: J8.63
MCU_GPIO37: J6.88 J7.61 | length 12.5
  Top w0.254: J6.88@47.673,-40.972 47.673,-37.925 53.877,-31.721 53.877,-31.213 J7.61@53.975,-31.115
MCU_GPIO37_1: J8.61
MCU_GPIO40: J6.89 J7.64 | length 16.6
  Mid1 w0.152: v1(48.473,-43.688) 48.473,-39.792 54.61,-33.655 54.61,-30.48 J7.64@55.245,-29.845
MCU_GPIO40_1: J8.64
MCU_GPIO41: J6.91 J7.66 | length 16.8
  Mid1 w0.152: v1(49.273,-43.688) 49.273,-39.5 55.88,-32.893 55.88,-30.48 J7.66@56.515,-29.845
MCU_GPIO44: J6.92 J7.65 | length 13.1
  Top w0.254: J6.92@49.273,-40.972 49.273,-38.437 52.363,-35.347 52.366,-35.347 53.931,-33.782 54.356,-33.782 56.417,-31.721 56.417,-31.213 J7.65@56.515,-31.115
MCU_GPIO47: J6.93 J7.68 | length 17
  Mid1 w0.152: v1(50.073,-43.688) 50.073,-39.245 57.15,-32.168 57.15,-30.48 J7.68@57.785,-29.845
MCU_GPIO48: J6.99 J7.72 | length 17.1
  Mid1 w0.152: v1(52.473,-43.688) 52.473,-39.221 59.694,-32 59.694,-30.476 J7.72@60.325,-29.845
MCU_GPIO49: J6.101 J7.74 | length 17.3
  Mid1 w0.152: v1(53.273,-43.688) 53.273,-39.945 60.96,-32.258 60.96,-30.442 61.557,-29.845 J7.74@61.595,-29.845
MCU_GPIO50: J6.103 J7.76 | length 17.5
  Mid1 w0.152: v1(54.073,-43.688) 54.073,-40.923 62.23,-32.766 62.23,-30.48 J7.76@62.865,-29.845
MCU_GPIO51: J6.105 J7.78 | length 17.7
  Mid1 w0.152: v1(54.873,-43.688) 54.873,-41.266 63.5,-32.639 63.5,-30.442 64.097,-29.845 J7.78@64.135,-29.845
MCU_GPIO52: J6.107 J7.80 | length 17.9
  Mid1 w0.152: v1(55.673,-43.688) 55.673,-41.257 64.77,-32.16 64.77,-30.48 J7.80@65.405,-29.845
MCU_GPIO53_3: J6.109
  other v1: 56.473,-43.688
MCU_GPIO54: J6.100 J7.71 | length 14.2
  Top w0.254: J6.100@52.473,-40.972 52.473,-37.757 54.883,-35.347 56.728,-35.347 60.29,-31.785 60.29,-31.15 J7.71@60.325,-31.115
MCU_GPIO55: J6.102 J7.73 | length 14.7
  Top w0.254: J6.102@53.273,-40.972 53.273,-37.913 55.331,-35.855 57.744,-35.855 61.56,-32.039 61.56,-31.15 J7.73@61.595,-31.115
MCU_GPIO56: J6.104 J7.75 | length 15
  Top w0.254: J6.104@54.073,-40.972 54.073,-38.129 55.839,-36.363 58.379,-36.363 62.865,-31.877 J7.75@62.865,-31.115
MCU_GPIO57: J6.106 J7.77 | length 15.4
  Top w0.254: J6.106@54.873,-40.972 54.873,-38.048 56.049,-36.871 59.014,-36.871 64.015,-31.87 64.015,-31.235 J7.77@64.135,-31.115
MCU_GPIO58: J6.94 J7.67 | length 13.6
  Top w0.254: J6.94@50.073,-40.972 50.073,-38.446 54.229,-34.29 55.245,-34.29 57.75,-31.785 57.75,-31.15 J7.67@57.785,-31.115
MCU_GPIO59: J6.95 J7.70 | length 17.2
  Mid1 w0.152: v1(50.873,-43.688) 50.873,-39.678 58.42,-32.131 58.42,-30.479 J7.70@59.055,-29.845
MCU_GPIO60: J6.96 J7.69 | length 14.1
  Top w0.254: J6.96@50.873,-40.972 50.873,-38.449 54.483,-34.839 55.966,-34.839 59.02,-31.785 59.02,-31.15 J7.69@59.055,-31.115
MCU_GPIO61: J6.108 J7.79 | length 15.7
  Top w0.254: J6.108@55.673,-40.972 55.673,-38.434 56.728,-37.379 59.769,-37.379 65.367,-31.781 65.367,-31.153 J7.79@65.405,-31.115
MCU_TCK_3: J6.5
MCU_TMS_3: J6.3
MCU_TRSTn_3: J6.4
NetC3_1: C3.1 U1.5 | length 1.2
  Bottom w0.254: C3.1@62.484,-8.452 63.616,-8.452 63.639,-8.429 U1.5@63.639,-8.404
NetC3_2: C3.2 L2.1 U1.3 | length 5.2
  Bottom w0.254: L2.1@60.071,-9.017 60.071,-9.376 60.244,-9.549 60.603,-9.549 60.706,-9.652 C3.2@62.484,-9.652 62.552,-9.584 63.016,-9.584 63.381,-9.219 63.897,-9.219 64.119,-9.441 64.119,-9.864 U1.3@64.139,-9.884
NetC109_2: C109.2 R21.1 R64.1 U12.1 U12.2 | length 6.8
  Top w0.3: U12.1@52.515,-8.847 U12.2@52.515,-6.947 ; U12.1@52.515,-8.697 C109.2@52.514,-10.103 R64.1@54.292,-10.103 R21.1@54.292,-8.382
NetC111_1: C111.1 R73.2 U14.1 | length 4.7
  Top w0.254: C111.1@21.717,-2.877 21.663,-2.931 21.663,-4.623 21.663,-4.779 21.663,-5.112 U14.1@21.49,-5.285 23.481,-5.285 R73.2@23.622,-5.426
NetC112_1: C112.1 R76.2 U14.2 | length 9.6
  Top w0.254: C112.1@20.32,-2.877 20.32,-5.185 U14.2@20.22,-5.285 20.34,-5.405 20.34,-6.291 20.488,-6.44 24.894,-6.44 25.635,-5.699 25.735,-5.699 25.908,-5.526 R76.2@25.908,-5.426
NetC113_1: C113.1 R74.2 U15.1 | length 16.8
  Mid1 w0.152: v1(12.245,-3.81) 13.007,-4.572 13.961,-5.526 24.474,-5.526 24.631,-5.368 v1(24.728,-5.368)
  Bottom w0.152: v1(24.728,-5.368) 24.796,-5.436 24.976,-5.436 24.995,-5.455 R74.2@25.906,-5.455
  Bottom w0.254: U15.1@12.245,-5.285 C113.1@12.245,-2.984
NetC114_1: C114.1 R77.2 U15.2 | length 13.3
  Mid1 w0.152: v1(13.499,-3.794) 13.512,-3.794 14.417,-4.699 22.339,-4.699 22.347,-4.691 22.538,-4.691 v1(22.606,-4.623)
  Bottom w0.152: v1(22.606,-4.623) 23.31,-5.326 23.614,-5.326 R77.2@23.749,-5.461
  Bottom w0.254: v1(13.499,-3.794) 13.515,-3.81 U15.2@13.515,-5.285 ; v1@13.515,-3.794 C114.1@13.515,-2.984
NetC118_1: C118.1 R79.2 U14.5 | length 3.4
  Top w0.254: R79.2@16.291,-1.905 16.41,-2.024 U14.5@16.41,-5.285
NetC119_1: C119.1 R80.2 U15.5 | length 3.6
  Bottom w0.254: U15.5@17.325,-5.285 17.479,-5.131 C119.1@17.479,-3.048 17.479,-1.74 R80.2@17.499,-1.72
NetC120_2: C120.2 R78.2 U13.5 | length 7.3
  Top w0.3: C120.2@6.604,-17.307 C120.2@6.604,-17.207 ; U13.5@6.63,-15.035 6.604,-15.061 C120.2@6.604,-17.207 ; R78.2@10.12,-19.864 10.102,-19.846 10.102,-19.189 8.12,-17.207 C120.2@6.604,-17.207
NetC121_2: C121.2 R75.2 U13.4 | length 7.7
  Top w0.3: C121.2@5.334,-17.307 5.334,-16.165 5.227,-16.058 v1(5.227,-16.002) 5.267,-15.962 5.267,-15.128 U13.4@5.36,-15.035 ; v1(6.985,-19.812) R75.2@7.747,-19.812
  Mid1 w0.3: v1(5.227,-16.002) 6.985,-17.76 v1(6.985,-19.812)
NetC122_2: C122.2 R72.2 U13.3 | length 10.8
  Top w0.254: C122.2@3.952,-17.169 3.637,-17.169 3.576,-17.108 v1(3.523,-17.108) 3.952,-17.108 3.998,-17.063 3.998,-15.127 U13.3@4.09,-15.035 ; v1(8.802,-19.065) 8.85,-19.114 8.85,-19.818 R72.2@8.925,-19.893
  Bottom w0.254: v1(3.523,-17.108) 3.523,-18.763 3.937,-19.177 v1@8.636,-19.177
NetC125_2: C125.2 R81.2 U14.6 | length 3.9
  Top w0.254: C125.2@13.742,-2.877 R81.2@14.986,-2.877 14.986,-2.977 15.159,-3.15 15.164,-3.15 15.313,-3.299 15.313,-5.112 U14.6@15.14,-5.285
NetC126_2: C126.2 R82.2 U15.6 | length 3.6
  Bottom w0.254: U15.6@18.595,-5.285 18.595,-3.285 18.796,-3.084 C126.2@18.796,-2.984 19.98,-2.984 R82.2@19.989,-2.993
NetJ4_2: J4.2
NetJ4_3: J4.3
NetJ4_13: J4.13
NetJ4_17: J4.17
NetJ5_23: 
NetJ6_6: J6.6
NetJ6_8: J6.8
NetJ6_16: J6.16
NetJ6_32: J6.32
NetJ6_41: J6.41
  other v1: 26.073,-43.688
NetJ6_42: J6.42
NetJ6_43: J6.43
  other v1: 26.873,-43.688
NetJ6_44: J6.44
NetJ6_45: J6.45
  other v1: 27.673,-43.688
NetJ6_66: J6.66
NetJ6_110: J6.110
NetJ6_113: J6.113
NetJ6_114: J6.114
NetJ6_115: J6.115
NetJ6_116: J6.116
NetJ6_117: J6.117
NetJ6_118: J6.118
NetJ6_119: J6.119
NetJ6_120: J6.120
NetR3_2: R3.2 U1.7 | length 2.6
  Bottom w0.254: U1.7@64.639,-8.404 64.659,-8.384 64.659,-7.961 64.881,-7.739 66.54,-7.739 R3.2@66.675,-7.874
NetR4_1: R4.1 R5.2 U9.4 | length 5.4
  Bottom w0.3: R4.1@4.027,-14.942 4.041,-14.942 4.191,-15.092 4.191,-17.78 4.506,-18.095 U9.4@6.447,-18.095 U9.4@6.379,-18.163
NetR6_1: R6.1 R20.1 U1.8 | length 3.3
  Bottom w0.254: U1.8@65.139,-8.404 65.139,-8.589 65.162,-8.612 65.347,-8.612 65.879,-9.144 R20.1@66.71,-9.144 R6.1@66.71,-10.414
NetR19_1: R19.1 U1.1 | length 2.8
  Bottom w0.254: U1.1@65.139,-9.884 65.139,-10.069 65.162,-10.092 65.337,-10.092 65.659,-10.414 65.659,-11.176 66.04,-11.557 R19.1@66.71,-11.557
NetR85_VS1_2: R85_VS1.2 R112_VS1.1 U16_VS1.3 | length 5.3
  Top w0.203: U16_VS1.3@32.827,-11.754 32.827,-11.555 33.025,-11.357 33.224,-11.357 33.671,-10.91 33.671,-10.572 34.21,-10.033 35.941,-10.033 R112_VS1.1@35.941,-8.89
NetR85_VS2_2: R85_VS2.2 R112_VS2.1 U16_VS2.3 | length 3.5
  Top w0.254: U16_VS2.3@45.527,-11.335 45.743,-11.119 R85_VS2.2@47.498,-11.119 R112_VS2.1@47.498,-9.652
NetR90_VS1_2: R90_VS1.2 R114_VS1.1 U16_VS1.4 | length 4.6
  Top w0.254: R114_VS1.1@31.277,-7.401 31.377,-7.401 31.55,-7.574 31.55,-7.727 32.454,-8.631 32.654,-8.631 U16_VS1.4@32.827,-8.804 ; U16_VS1.4@32.827,-9.004 U16_VS1.4@32.827,-8.804 ; R90_VS1.2@34.557,-7.731 34.481,-7.807 33.824,-7.807 U16_VS1.4@32.827,-8.804
NetR90_VS2_2: R90_VS2.2 R114_VS2.1 U16_VS2.4 | length 15
  Top w0.152: v1(43.621,-12.633) 43.689,-12.701 43.689,-12.915 44.18,-13.406 47.614,-13.406 48.108,-12.913 48.108,-10.312 R114_VS2.1@48.768,-9.652
  Top w0.203: v1(45.358,-9.623) v1@45.416,-9.565 ; U16_VS2.4@45.416,-8.896 U16_VS2.4@45.527,-8.785
  Top w0.254: R90_VS2.2@42.037,-12.792 43.393,-12.792 43.552,-12.633 v1(43.621,-12.633) ; v1@45.416,-9.565 U16_VS2.4@45.416,-8.896
  Bottom w0.254: v1(43.621,-12.633) 43.634,-12.633 45.358,-10.909 v1(45.358,-9.623)
NetR91_VS1_2: R91_VS1.2 R115_VS1.1 U17_VS1.3 | length 5.4
  Bottom w0.203: R115_VS1.1@34.544,-8.855 R91_VS1.2@34.544,-10.322 34.544,-10.422 34.742,-10.62 34.786,-10.62 35.32,-11.154 U17_VS1.3@37.658,-11.154 37.658,-11.303 U17_VS1.3@37.46,-11.501
NetR91_VS2_2: R91_VS2.2 R115_VS2.1 U17_VS2.3 | length 6.6
  Bottom w0.203: R91_VS2.2@46.355,-10.83 46.355,-10.887 46.553,-11.086 46.824,-11.086 47.581,-11.843 48.431,-11.843 49.723,-10.55 U17_VS2.3@49.723,-9.703
  Bottom w0.254: R91_VS2.2@46.355,-10.541 R115_VS2.1@46.355,-9.144
NetR95_VS1_2: R95_VS1.2 R116_VS1.1 U17_VS1.4 | length 4.3
  Bottom w0.203: R95_VS1.2@35.886,-9.179 R95_VS1.2@35.941,-9.124 ; R95_VS1.2@35.941,-9.335 R95_VS1.2@35.941,-9.124 ; R116_VS1.1@35.976,-6.858 35.976,-8.404 ; U17_VS1.4@37.658,-8.404 35.976,-8.404 ; R95_VS1.2@35.941,-9.124 35.976,-9.089 35.976,-8.404
NetR95_VS2_2: R95_VS2.2 R116_VS2.1 U17_VS2.4 | length 3.8
  Bottom w0.254: R95_VS2.2@48.006,-9.814 R116_VS2.1@48.006,-8.612 ; R116_VS2.1@48.006,-8.544 48.006,-8.444 48.179,-8.271 48.279,-8.271 49.424,-7.126 49.55,-7.126 49.723,-6.953 U17_VS2.4@49.723,-6.753
NetU1_6: U1.6
NetU11_4: U11.4
NetU13_7: U13.7
NetU13_9: U13.9
NetU13_10: U13.10
NetU14_7: U14.7
NetU14_12: U14.12
NetU14_13: U14.13
NetU15_7: U15.7
NetU15_12: U15.12
NetU15_13: U15.13
PFC_OK: J4.6 R72.1 | length 1.6
  Top w0.3: J4.6@8.85,-22.6 8.85,-21.064 R72.1@8.886,-21.028
PFC_OK_s_1: R43.1 U13.14 | length 2.1
  Top w0.3: U13.14@4.064,-5.259 U13.14@4.09,-5.285 4.09,-3.258 R43.1@4.064,-3.232
PH1_PRI_PWMA_1: R30.1 R69.1 R73.1 | length 38.2
  Top w0.152: v1(41.91,-23.038) 41.946,-23.001 41.946,-22.697 42.139,-22.504 42.385,-22.504 42.664,-22.225 R30.1@43.342,-22.225
  Top w0.3: R69.1@23.622,-2.886 23.622,-3.983 R73.1@23.622,-4.226 23.622,-4.133 23.772,-3.983 24.168,-3.983 v1(24.744,-3.407)
  Mid1 w0.152: v1(24.744,-3.407) 24.766,-3.407 26.822,-5.464 26.822,-19.319 30.211,-22.708 41.138,-22.708 41.474,-23.043 41.905,-23.043 v1(41.91,-23.038)
PH1_PRI_PWMB_1: R32.1 R68.1 R76.1 | length 35.4
  Top w0.3: R76.1@25.908,-4.226 25.908,-4.126 26.058,-3.976 26.284,-3.976 26.568,-3.692 26.719,-3.692 v1(26.759,-3.652) ; R68.1@25.908,-2.886 25.989,-2.967 25.989,-3.976 R76.1@25.989,-4.226
  Mid1 w0.152: v1(26.759,-3.652) 27.534,-4.427 27.534,-19.025 30.505,-21.996 v1@42.228,-21.996
  Bottom w0.152: v1(42.164,-21.971) 42.177,-21.971 42.431,-22.225 R32.1@43.342,-22.225
PH1_SEC_PWMAH: J5.11 R99.1 | length 19.9
  Top w0.152: v1(47.244,-14.478) 47.312,-14.41 47.312,-13.967 47.52,-13.759 47.76,-13.759 48.46,-13.059 49.237,-12.282 55.162,-12.282 56.261,-11.183 56.261,-4.106 J5.11@55.555,-3.4
  Bottom w0.152: R99.1@46.99,-15.556 46.99,-14.732 v1(47.244,-14.478)
PH1_SEC_PWMAL: J5.10 R8.1 R100.1 | length 20
  Top w0.152: R8.1@48.231,-15.691 48.298,-15.623 v1(48.298,-14.93) 48.335,-14.894 48.64,-14.894 48.92,-14.613 48.92,-13.821 50.104,-12.638 55.64,-12.638 56.769,-11.509 56.769,-3.456 J5.10@56.825,-3.4
  Bottom w0.152: R100.1@48.133,-15.556 48.298,-15.391 v1(48.298,-14.93)
PH1_SEC_PWMBH: J5.9 R23.1 R37.1 | length 22.6
  Top w0.152: R23.1@46.99,-15.748 47.214,-15.524 47.214,-15.397 47.768,-14.843 47.768,-14.71 48.298,-14.18 v1(48.298,-14.087) ; R37.1@49.398,-15.691 49.398,-15.591 49.622,-15.367 49.622,-15.29 49.634,-15.278 49.634,-13.611 50.251,-12.993 55.788,-12.993 57.125,-11.656 57.125,-4.53 58.095,-3.56 J5.9@58.095,-3.4
  Bottom w0.152: v1(48.298,-14.087) v1@49.543,-14.087
  other v1: 49.634,-14.106
PH1_SEC_PWMBL: J5.8 R7.1 R38.1 | length 25
  Top w0.152: v1(50.452,-13.916) v1@50.472,-13.936 ; R38.1@50.565,-15.691 50.472,-15.598 50.472,-13.916 50.472,-13.807 50.93,-13.349 55.935,-13.349 57.48,-11.804 57.48,-5.285 J5.8@59.365,-3.4
  Bottom w0.152: R7.1@45.847,-15.556 45.847,-14.834 46.768,-13.913 47.366,-13.913 47.722,-13.557 50.093,-13.557 v1(50.452,-13.916)
PH2_PRI_PWMA_1: R33.1 R70.1 R77.1 | length 37.2
  Mid1 w0.152: v1(24.738,-4.34) 25.195,-4.34 26.47,-5.615 26.47,-19.465 27.178,-20.173 27.178,-20.178 29.472,-22.471 29.733,-22.733 29.738,-22.733 30.065,-23.06 40.848,-23.06 41.375,-23.588 42.33,-23.588 v1(42.344,-23.602)
  Bottom w0.152: v1(42.344,-23.602) 42.44,-23.602 42.595,-23.446 R33.1@43.342,-23.446
  Bottom w0.3: R70.1@23.749,-2.886 R77.1@23.749,-4.261 23.833,-4.345 24.733,-4.345 v1(24.738,-4.34)
PH2_PRI_PWMB_1: R35.1 R71.1 R74.1 | length 36.6
  Top w0.152: v1(43.18,-24.257) 43.18,-24.161 43.342,-23.999 R35.1@43.342,-23.719
  Mid1 w0.152: v1(26.759,-4.416) 27.178,-4.835 27.178,-19.172 30.358,-22.352 41.529,-22.352 41.681,-22.504 42.316,-22.504 43.342,-23.53 43.342,-23.999 43.18,-24.161 v1(43.18,-24.257)
  Bottom w0.152: R74.1@25.906,-4.255 R74.1@25.908,-4.253
  Bottom w0.3: R74.1@25.906,-4.255 26.027,-4.376 26.719,-4.376 v1(26.759,-4.416) ; R74.1@25.908,-4.253 R71.1@25.908,-2.886
PH2_SEC_PWMAH: J5.7 R40.1 | length 17.8
  Top w0.152: R40.1@51.733,-15.691 51.733,-14.91 52.312,-14.33 52.938,-13.704 56.082,-13.704 57.836,-11.951 57.836,-6.199 J5.7@60.635,-3.4
PH2_SEC_PWMAL: J5.6 R10.1 R41.1 | length 22.5
  Top w0.152: R41.1@54.068,-15.691 54.068,-14.303 v1(54.133,-14.238) ; v1@54.133,-14.204 54.289,-14.204 56.086,-14.204 58.191,-12.098 58.191,-7.114 J5.6@61.905,-3.4
  Bottom w0.152: R10.1@49.149,-15.556 49.245,-15.46 49.245,-15.017 49.491,-14.771 50.283,-14.771 50.638,-14.416 50.907,-14.416 51.2,-14.122 53.624,-14.122 53.739,-14.238 v1(54.133,-14.238)
PH2_SEC_PWMBH: J5.5 R24.1 R101.1 | length 21.8
  Top w0.152: R24.1@55.235,-15.656 55.235,-14.977 55.345,-14.868 v1(55.345,-14.771) 55.434,-14.771 55.612,-14.593 56.199,-14.593 58.547,-12.246 58.547,-8.028 J5.5@63.175,-3.4
  Bottom w0.152: R101.1@50.165,-15.556 50.389,-15.332 50.389,-15.168 50.785,-14.771 51.054,-14.771 51.347,-14.478 53.476,-14.478 53.77,-14.771 v1(55.345,-14.771)
PH2_SEC_PWMBL: J5.4 R9.1 R102.1 | length 23.2
  Top w0.152: R9.1@52.9,-15.691 52.979,-15.612 v1(52.979,-15.011) ; v1(56.906,-14.636) 57.5,-14.636 58.928,-13.208 58.928,-8.255 62.738,-4.445 63.4,-4.445 J5.4@64.445,-3.4
  Bottom w0.152: R102.1@51.308,-15.556 51.532,-15.332 51.532,-15.101 51.621,-15.011 v1(52.979,-15.011) 52.979,-15.24 53.741,-16.002 56.134,-16.002 56.906,-15.23 v1(56.906,-14.636)
RX-PFC: J4.8 U13.6 | length 9
  Top w0.3: U13.6@7.9,-15.035 7.905,-15.04 7.905,-16.134 11.39,-19.619 J4.8@11.39,-22.6
TS_Debug_3: C104.2 pad.5@3.81,-34.845 R60.1 | length 8.6
  Top w0.254: pad.5@3.81,-34.845 4.433,-35.468 C104.2@5.842,-35.468 ; C104.2@5.842,-35.56 10.76,-35.56 11.411,-34.909 11.511,-34.909 11.684,-34.736 R60.1@11.684,-34.636
TX-PFC: J4.7 R78.1 | length 1.3
  Top w0.3: J4.7@10.12,-22.6 10.16,-22.56 10.16,-21.376 R78.1@10.12,-21.336
URAT1_RX_s_1: R46.1 U13.12 | length 1.8
  Top w0.3: U13.12@6.63,-5.285 6.63,-3.657 R46.1@6.779,-3.508
URAT1_TX_s_1: R48.2 U13.11 | length 64.2
  Top w0.152: R48.2@56.861,-15.621 R48.2@56.896,-15.656 ; R48.2@56.896,-15.367 56.931,-15.332 57.332,-15.332 57.435,-15.23 v1(57.531,-15.23)
  Top w0.3: U13.11@7.9,-5.285 8.05,-5.135 8.05,-4.094 9.787,-2.357 9.787,-2.298 v1(9.827,-2.258)
  Mid1 w0.152: v1(9.827,-2.258) 11.323,-0.762 26.619,-0.762 28.956,-3.099 28.956,-11.811 32.69,-15.545 55.606,-15.545 55.921,-15.23 v1(57.531,-15.23)
URAT2_RX: J5.3 R50.1 | length 16.8
  Top w0.152: 60.014,-15.621 60.395,-15.24 63.792,-15.24 66.04,-12.992 66.04,-4.776 65.715,-4.451 J5.3@65.715,-3.4
URAT2_TX: J5.2 R52.2 | length 16.8
  Top w0.152: R52.2@61.047,-15.969 64.004,-15.969 66.421,-13.552 66.421,-3.964 J5.2@66.985,-3.4
Vcm_bias_1: C129_VS1.2 C129_VS2.2 C134_VS1.1 C134_VS2.1 R22.2 R64.2 R85_VS1.1 R85_VS2.1 R91_VS1.1 R91_VS2.1 | length 27.8
  Top w0.2: v1(38.529,-13.583) 38.529,-13.589 39.703,-14.763 41.752,-14.763 v1(43.053,-13.462)
  Top w0.254: C129_VS1.2@34.544,-10.83 34.544,-10.93 34.717,-11.103 34.817,-11.103 35.427,-11.713 35.877,-11.713 R85_VS1.1@35.941,-11.649 ; C129_VS2.2@45.896,-12.827 46.019,-12.704 46.504,-12.704 46.743,-12.465 v1(46.78,-12.465) 46.786,-12.472 47.345,-12.472 R85_VS2.1@47.498,-12.319 ; R22.2@52.514,-11.43 v1(53.34,-11.43) 54.165,-11.43 R64.2@54.292,-11.303
  Bottom w0.2: C134_VS1.1@36.573,-12.704 36.673,-12.704 36.873,-12.904 36.873,-13.004 37.458,-13.589 38.522,-13.589 v1(38.529,-13.583)
  Bottom w0.203: v1(46.78,-12.465) 46.832,-12.465 47.051,-12.246 48.598,-12.246 49.701,-11.142 50.286,-11.142 C134_VS2.1@50.287,-11.141
  Bottom w0.254: R91_VS1.1@34.544,-11.522 34.574,-11.552 35.107,-11.552 35.219,-11.664 35.307,-11.664 v1(35.355,-11.713) ; v1@35.355,-11.595 35.355,-11.644 35.473,-11.761 35.63,-11.761 36.3,-12.431 36.3,-12.531 36.473,-12.704 C134_VS1.1@36.573,-12.704 ; v1(43.053,-13.462) 44.196,-13.462 45.193,-12.465 v1(46.78,-12.465) ; C134_VS2.1@50.287,-11.141 50.387,-11.141 50.56,-11.314 50.56,-11.414 50.917,-11.771 52.999,-11.771 v1(53.34,-11.43)
VCR-N_VS1: R16.2 R95_VS1.1 U17_VS1.1 | length 9.6
  Top w0.152: v1(40.042,-11.177) 40.529,-11.664 40.529,-14.194 v1(40.535,-14.2)
  Bottom w0.152: R16.2@40.047,-15.148 40.126,-15.069 40.126,-14.609 v1(40.535,-14.2)
  Bottom w0.254: R95_VS1.1@35.886,-10.379 35.886,-10.333 36.059,-10.16 39.26,-10.16 39.522,-10.422 39.522,-11.118 U17_VS1.1@39.558,-11.154 U17_VS1.1@39.581,-11.177 ; U17_VS1.1@39.462,-11.184 39.47,-11.177 U17_VS1.1@39.581,-11.177 ; v1(40.042,-11.177) U17_VS1.1@39.581,-11.177
VCR-N_VS2: R18.2 R95_VS2.1 U17_VS2.1 | length 17.6
  Mid1 w0.152: v1@41.184,-14.138 v1(41.246,-14.2) 41.905,-14.859 45.487,-14.859 48.641,-11.705 v1(48.641,-10.795)
  Bottom w0.152: v1(41.246,-14.2) 41.275,-14.229 R18.2@41.275,-15.148
  Bottom w0.254: R95_VS2.1@48.006,-11.141 48.006,-11.041 48.179,-10.868 48.499,-10.868 48.791,-10.576 48.791,-9.03 49.55,-8.271 51.007,-8.271 51.621,-8.884 51.621,-9.501 U17_VS2.1@51.623,-9.503
VCR-P_VS1: R15.2 R90_VS1.1 U16_VS1.1 | length 10.1
  Top w0.203: U16_VS1.1@30.927,-11.754 30.927,-11.068 31.165,-10.83 32.658,-10.83 34.258,-9.229 34.358,-9.229 34.557,-9.031 R90_VS1.1@34.557,-8.931
  Bottom w0.203: R15.2@29.718,-15.148 29.718,-15.048 29.916,-14.85 30.016,-14.85 31.046,-13.82 v1(31.046,-10.949)
VCR-P_VS2: R17.2 R90_VS2.1 U16_VS2.1 | length 9.8
  Top w0.254: R90_VS2.1@42.037,-11.592 v1@42.669,-11.592 ; v1(42.669,-11.427) v1@42.669,-11.592 ; v1@42.804,-11.582 42.794,-11.592 v1@42.669,-11.592 ; v1@42.814,-11.592 43.57,-11.592 U16_VS2.1@43.627,-11.535
  Bottom w0.152: R17.2@36.537,-15.148 36.605,-15.08 36.605,-14.609 36.764,-14.45 37.986,-14.45 38.321,-14.116 38.859,-14.116 40.303,-12.672 41.499,-12.672 42.669,-11.502 v1(42.669,-11.427)
VPRI: J5.17 pad.5@47.91,-22.6 R1.2 | length 15.1
  Mid2 w0.2: v1(34.976,-21.463) 34.993,-21.463 35.247,-21.209 43.532,-21.209 43.912,-21.588 47.496,-21.588 47.826,-21.918 47.826,-22.516 pad.5@47.91,-22.6
  Bottom w0.2: R1.2@34.636,-22.479 34.636,-21.803 v1(34.976,-21.463)
VSEC: J5.16 R2.2 | length 22.7
  Top w0.152: v1(36.093,-13.922) 36.12,-13.896 36.12,-13.571 38.08,-11.611 38.08,-8.46 39.555,-6.985 v1(42.418,-6.985)
  Bottom w0.152: R2.2@33.909,-15.148 33.909,-14.405 34.434,-13.88 36.051,-13.88 v1(36.093,-13.922) ; v1(42.418,-6.985) 44.958,-4.445 48.16,-4.445 J5.16@49.205,-3.4
pads on no net: J6.181 J6.182 J6.185 J6.186

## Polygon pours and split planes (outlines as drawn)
DGND-s on Mid2 "Mid2-DGND-s" (solid, remove dead copper, pour order 5): 0.635,-5.969 1.288,-6.508 24.988,-6.508 25.908,-7.428 25.908,-19.304 31.369,-24.765 68.072,-24.765 69.469,-23.368 69.469,-2.286 67.818,-0.635 1.397,-0.635 0.635,-1.397
DGND-s on Mid2 "DGND-S_L03_P000" (solid, remove dead copper, pour order 0): 2.54,-41.275 2.54,-31.115 12.7,-31.115 13.97,-29.845 13.97,-27.559 65.151,-27.559 66.675,-29.083 66.675,-42.545 61.595,-47.625 8.89,-47.625
5Vcc-s on Bottom "5VCC-S_L04_P002" (solid, remove dead copper, pour order 2): 2.54,-41.275 2.54,-31.496 12.7,-31.496 14.224,-29.972 14.224,-28.067 65.659,-28.067 66.675,-29.083 66.675,-42.545 61.595,-47.625 8.89,-47.625
5Vcc-s on Mid1 "5VCC-S_L02_P007" (solid, remove dead copper, pour order 7): 2.54,-41.275 2.54,-31.115 12.7,-31.115 13.97,-29.845 13.97,-27.559 65.151,-27.559 66.675,-29.083 66.675,-42.545 61.595,-47.625 8.89,-47.625
DGND-s on Mid1 "Mid1-DGND-s" (solid, remove dead copper, pour order 6): 0.635,-5.969 1.288,-6.508 25.993,-6.508 26.416,-6.931 26.416,-19.812 31.369,-24.765 68.072,-24.765 69.469,-23.368 69.469,-2.286 67.818,-0.635 1.397,-0.635 0.635,-1.397

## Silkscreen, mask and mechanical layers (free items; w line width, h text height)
Top Overlay:
  lines w0.15: 17.78,-34.29 17.78,-27 ; 55.88,-34.925 55.88,-27
  lines w0.2: 17.78,-32.385 55.88,-32.385 ; 17.78,-28.448 55.88,-28.448
  text "GNDs" at 65.811,-8.611 h0.89
  text "12Vs" at 62.636,-14.961 h0.89
  text "63" at 66.319,-17.628 h0.89
  text "5" at 28.727,-18.39 h0.89
  text "GNDp" at 0.66,-20.887 h0.89
  text "12Vp" at 17.297,-21.014 h0.89
  text "6" at 28.6,-21.692 h0.89
  text "PMP41017" at 50.95,-22.71 h0.7
  text "Interposer for C2000" at 51.077,-24.128 h0.7
  text "64" at 66.319,-24.232 h0.89
  text "6" at 18.152,-27.915 h0.89
  text "64" at 53.866,-27.915 h0.89
  text "5" at 18.186,-33.757 h0.89
  text "63" at 53.873,-33.757 h0.89
  text "DACA" at 7.137,-34.9 h0.89
  text "Interposer for C2000" at 28.979,-36.193 h0.7
  text "AGND" at 7.264,-37.573 h0.89
Bottom Overlay:
  lines w0.1: 17.78,-32.385 17.78,-27.305 ; 55.88,-33.655 55.88,-28.575
  text "5" at 29.185,-18.39 h0.89
  text "64" at 68.428,-21.946 h0.89
  text "64" at 55.474,-27.915 h0.89
  text "5" at 18.771,-33.122 h0.89
  text "DACA" at 8.611,-35.154 h0.89
  text "AGND" at 8.23,-37.821 h0.89
Mechanical 1:
  lines w0.1: 70,0 ccw(c70,0.005) 70.005,0.005 ; 0,-26 0,-48.641 70,-48.641 70,-26 ; 0,-26 0,-0.017 70.005,-0.017 70,-0.017 70,-26 ; 0,-26 70,-26
Mechanical 3:
  lines w0.1: 0,-48.641 70,-48.641
Mechanical 15:
  circle w1.6: c2.5,-22.6 r1.6

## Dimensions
69.997,-29.003 to 25.15,-31.177 on Mechanical 3
0,-26 to 0,0 on Mechanical 3
70,-0.017 to 0,-0.017 on Mechanical 3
